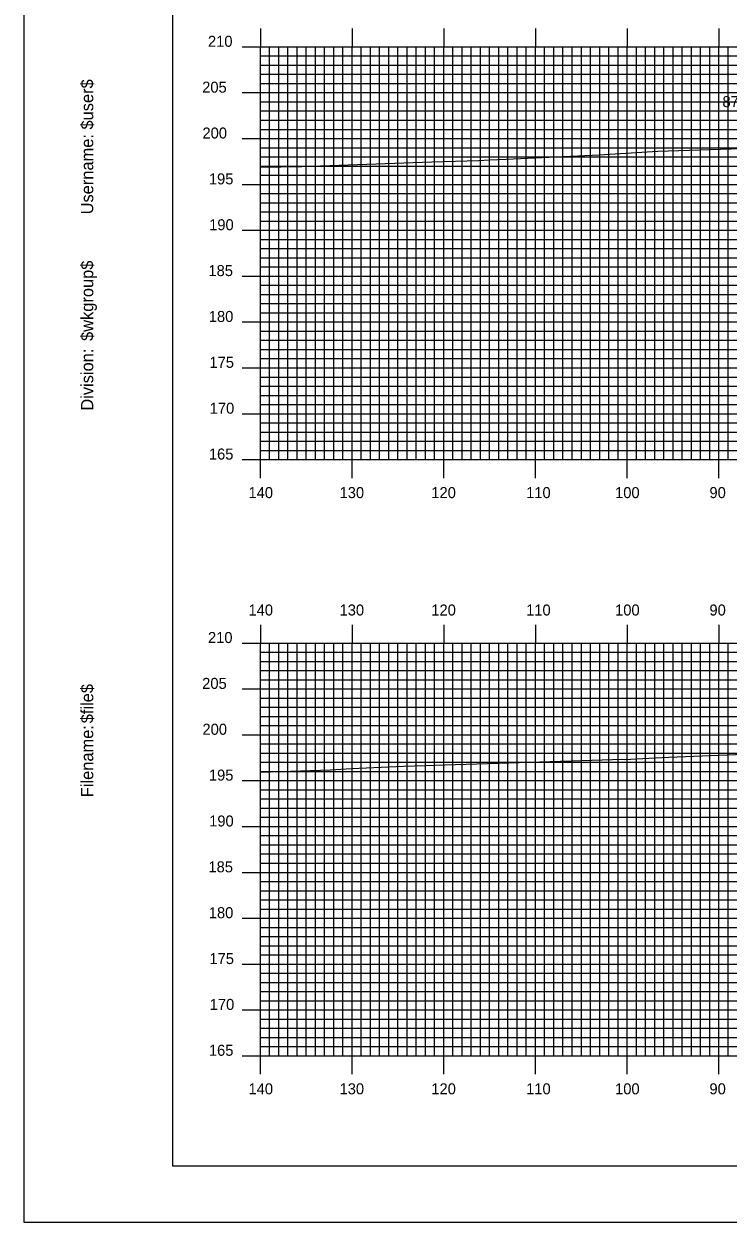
# Model space of a CAD drawing. Extents: x 1795633 to 1795976, y 442591 to 442811.
# Drawn here: x 1795633.1 to 1795709.9, y 442590.5 to 442721.2 of the extents above; entities that cross this region are included whole.
import ezdxf

# ---------------------------------------------------------------- set-up
doc = ezdxf.new("R2010")
doc.units = 0
for name, color, linetype in [('BORDER', 7, 'Continuous'), ('D_Text_Standard', 7, 'Continuous'), ('H_V ANNOTATION', 7, 'Continuous'), ('MAJOR', 7, 'Continuous'), ('MINOR', 7, 'Continuous'), ('PLOT BOUNDARY', 7, 'Continuous'), ('S_Roadway_Centerline', 7, 'Continuous')]:
    doc.layers.add(name, color=color, linetype=linetype)

msp = doc.modelspace()

# ---------------------------------------------------------------- linework, layer by layer
at = {"layer": 'BORDER'}
msp.add_lwpolyline([(1795649.28, 442596.67), (1795969.28, 442596.67), (1795969.28, 442806.67), (1795649.28, 442806.67)], close=True, dxfattribs=at)
at = {"layer": 'MAJOR'}
for p, q in [((1795658.88, 442720.67), (1795658.88, 442718.67)), ((1795668.88, 442720.67), (1795668.88, 442718.67)), ((1795678.88, 442720.67), (1795678.88, 442718.67)), ((1795688.88, 442720.67), (1795688.88, 442718.67)), ((1795698.88, 442720.67), (1795698.88, 442718.67)), ((1795708.88, 442720.67), (1795708.88, 442718.67)), ((1795656.88, 442718.67), (1795658.88, 442718.67)), ((1795658.88, 442718.67), (1795938.88, 442718.67)), ((1795658.88, 442673.67), (1795658.88, 442718.67)), ((1795658.88, 442673.67), (1795658.88, 442718.67)), ((1795658.88, 442718.67), (1795938.88, 442718.67)), ((1795668.88, 442673.67), (1795668.88, 442718.67)), ((1795678.88, 442673.67), (1795678.88, 442718.67)), ((1795688.88, 442673.67), (1795688.88, 442718.67)), ((1795698.88, 442673.67), (1795698.88, 442718.67)), ((1795708.88, 442673.67), (1795708.88, 442718.67)), ((1795656.88, 442713.67), (1795658.88, 442713.67)), ((1795658.88, 442713.67), (1795938.88, 442713.67)), ((1795656.88, 442708.67), (1795658.88, 442708.67)), ((1795658.88, 442708.67), (1795938.88, 442708.67)), ((1795656.88, 442703.67), (1795658.88, 442703.67)), ((1795658.88, 442703.67), (1795938.88, 442703.67)), ((1795656.88, 442698.67), (1795658.88, 442698.67)), ((1795658.88, 442698.67), (1795938.88, 442698.67)), ((1795656.88, 442693.67), (1795658.88, 442693.67)), ((1795658.88, 442693.67), (1795938.88, 442693.67)), ((1795656.88, 442688.67), (1795658.88, 442688.67)), ((1795658.88, 442688.67), (1795938.88, 442688.67)), ((1795656.88, 442683.67), (1795658.88, 442683.67)), ((1795658.88, 442683.67), (1795938.88, 442683.67)), ((1795656.88, 442678.67), (1795658.88, 442678.67)), ((1795658.88, 442678.67), (1795938.88, 442678.67)), ((1795656.88, 442673.67), (1795658.88, 442673.67)), ((1795658.88, 442673.67), (1795938.88, 442673.67)), ((1795658.88, 442673.67), (1795938.88, 442673.67)), ((1795658.88, 442671.66), (1795658.88, 442673.67)), ((1795668.88, 442671.66), (1795668.88, 442673.67)), ((1795678.88, 442671.66), (1795678.88, 442673.67)), ((1795688.88, 442671.66), (1795688.88, 442673.67)), ((1795698.88, 442671.66), (1795698.88, 442673.67)), ((1795708.88, 442671.66), (1795708.88, 442673.67)), ((1795658.88, 442655.67), (1795658.88, 442653.67)), ((1795668.88, 442655.67), (1795668.88, 442653.67)), ((1795678.88, 442655.67), (1795678.88, 442653.67)), ((1795688.88, 442655.67), (1795688.88, 442653.67)), ((1795698.88, 442655.67), (1795698.88, 442653.67)), ((1795708.88, 442655.67), (1795708.88, 442653.67)), ((1795656.88, 442653.67), (1795658.88, 442653.67)), ((1795658.88, 442653.67), (1795938.88, 442653.67)), ((1795658.88, 442608.67), (1795658.88, 442653.67)), ((1795658.88, 442608.67), (1795658.88, 442653.67)), ((1795658.88, 442653.67), (1795938.88, 442653.67)), ((1795668.88, 442608.67), (1795668.88, 442653.67)), ((1795678.88, 442608.67), (1795678.88, 442653.67)), ((1795688.88, 442608.67), (1795688.88, 442653.67)), ((1795698.88, 442608.67), (1795698.88, 442653.67)), ((1795708.88, 442608.67), (1795708.88, 442653.67)), ((1795656.88, 442648.67), (1795658.88, 442648.67)), ((1795658.88, 442648.67), (1795938.88, 442648.67)), ((1795656.88, 442643.67), (1795658.88, 442643.67)), ((1795658.88, 442643.67), (1795938.88, 442643.67)), ((1795656.88, 442638.67), (1795658.88, 442638.67)), ((1795658.88, 442638.67), (1795938.88, 442638.67)), ((1795656.88, 442633.67), (1795658.88, 442633.67)), ((1795658.88, 442633.67), (1795938.88, 442633.67)), ((1795656.88, 442628.67), (1795658.88, 442628.67)), ((1795658.88, 442628.67), (1795938.88, 442628.67)), ((1795656.88, 442623.67), (1795658.88, 442623.67)), ((1795658.88, 442623.67), (1795938.88, 442623.67)), ((1795656.88, 442618.67), (1795658.88, 442618.67)), ((1795658.88, 442618.67), (1795938.88, 442618.67)), ((1795656.88, 442613.67), (1795658.88, 442613.67)), ((1795658.88, 442613.67), (1795938.88, 442613.67)), ((1795656.88, 442608.67), (1795658.88, 442608.67)), ((1795658.88, 442608.67), (1795938.88, 442608.67)), ((1795658.88, 442608.67), (1795938.88, 442608.67)), ((1795658.88, 442606.66), (1795658.88, 442608.67)), ((1795668.88, 442606.66), (1795668.88, 442608.67)), ((1795678.88, 442606.66), (1795678.88, 442608.67)), ((1795688.88, 442606.66), (1795688.88, 442608.67)), ((1795698.88, 442606.66), (1795698.88, 442608.67)), ((1795708.88, 442606.66), (1795708.88, 442608.67))]:
    msp.add_line(p, q, dxfattribs=at)
at = {"layer": 'MINOR'}
for p, q in [((1795659.88, 442673.67), (1795659.88, 442718.67)), ((1795660.88, 442673.67), (1795660.88, 442718.67)), ((1795661.88, 442673.67), (1795661.88, 442718.67)), ((1795662.88, 442673.67), (1795662.88, 442718.67)), ((1795663.88, 442673.67), (1795663.88, 442718.67)), ((1795664.88, 442673.67), (1795664.88, 442718.67)), ((1795665.88, 442673.67), (1795665.88, 442718.67)), ((1795666.88, 442673.67), (1795666.88, 442718.67)), ((1795667.88, 442673.67), (1795667.88, 442718.67)), ((1795669.88, 442673.67), (1795669.88, 442718.67)), ((1795670.88, 442673.67), (1795670.88, 442718.67)), ((1795671.88, 442673.67), (1795671.88, 442718.67)), ((1795672.88, 442673.67), (1795672.88, 442718.67)), ((1795673.88, 442673.67), (1795673.88, 442718.67)), ((1795674.88, 442673.67), (1795674.88, 442718.67)), ((1795675.88, 442673.67), (1795675.88, 442718.67)), ((1795676.88, 442673.67), (1795676.88, 442718.67)), ((1795677.88, 442673.67), (1795677.88, 442718.67)), ((1795679.88, 442673.67), (1795679.88, 442718.67)), ((1795680.88, 442673.67), (1795680.88, 442718.67)), ((1795681.88, 442673.67), (1795681.88, 442718.67)), ((1795682.88, 442673.67), (1795682.88, 442718.67)), ((1795683.88, 442673.67), (1795683.88, 442718.67)), ((1795684.88, 442673.67), (1795684.88, 442718.67)), ((1795685.88, 442673.67), (1795685.88, 442718.67)), ((1795686.88, 442673.67), (1795686.88, 442718.67)), ((1795687.88, 442673.67), (1795687.88, 442718.67)), ((1795689.88, 442673.67), (1795689.88, 442718.67)), ((1795690.88, 442673.67), (1795690.88, 442718.67)), ((1795691.88, 442673.67), (1795691.88, 442718.67)), ((1795692.88, 442673.67), (1795692.88, 442718.67)), ((1795693.88, 442673.67), (1795693.88, 442718.67)), ((1795694.88, 442673.67), (1795694.88, 442718.67)), ((1795695.88, 442673.67), (1795695.88, 442718.67)), ((1795696.88, 442673.67), (1795696.88, 442718.67)), ((1795697.88, 442673.67), (1795697.88, 442718.67)), ((1795699.88, 442673.67), (1795699.88, 442718.67)), ((1795700.88, 442673.67), (1795700.88, 442718.67)), ((1795701.88, 442673.67), (1795701.88, 442718.67)), ((1795702.88, 442673.67), (1795702.88, 442718.67)), ((1795703.88, 442673.67), (1795703.88, 442718.67)), ((1795704.88, 442673.67), (1795704.88, 442718.67)), ((1795705.88, 442673.67), (1795705.88, 442718.67)), ((1795706.88, 442673.67), (1795706.88, 442718.67)), ((1795707.88, 442673.67), (1795707.88, 442718.67)), ((1795709.88, 442673.67), (1795709.88, 442718.67)), ((1795658.88, 442717.67), (1795938.88, 442717.67)), ((1795658.88, 442717.67), (1795660.88, 442717.67)), ((1795658.88, 442716.67), (1795938.88, 442716.67)), ((1795658.88, 442716.67), (1795660.88, 442716.67)), ((1795658.88, 442715.67), (1795938.88, 442715.67)), ((1795658.88, 442715.67), (1795660.88, 442715.67)), ((1795658.88, 442714.67), (1795938.88, 442714.67)), ((1795658.88, 442714.67), (1795660.88, 442714.67)), ((1795658.88, 442712.67), (1795938.88, 442712.67)), ((1795658.88, 442712.67), (1795660.88, 442712.67)), ((1795658.88, 442711.67), (1795938.88, 442711.67)), ((1795658.88, 442711.67), (1795660.88, 442711.67)), ((1795658.88, 442710.67), (1795938.88, 442710.67)), ((1795658.88, 442710.67), (1795660.88, 442710.67)), ((1795658.88, 442709.67), (1795938.88, 442709.67)), ((1795658.88, 442709.67), (1795660.88, 442709.67)), ((1795658.88, 442707.67), (1795938.88, 442707.67)), ((1795658.88, 442707.67), (1795660.88, 442707.67)), ((1795658.88, 442706.67), (1795938.88, 442706.67)), ((1795658.88, 442706.67), (1795660.88, 442706.67)), ((1795658.88, 442705.67), (1795938.88, 442705.67)), ((1795658.88, 442705.67), (1795660.88, 442705.67)), ((1795658.88, 442704.67), (1795938.88, 442704.67)), ((1795658.88, 442704.67), (1795660.88, 442704.67)), ((1795658.88, 442702.67), (1795938.88, 442702.67)), ((1795658.88, 442702.67), (1795660.88, 442702.67)), ((1795658.88, 442701.67), (1795938.88, 442701.67)), ((1795658.88, 442701.67), (1795660.88, 442701.67)), ((1795658.88, 442700.67), (1795938.88, 442700.67)), ((1795658.88, 442700.67), (1795660.88, 442700.67)), ((1795658.88, 442699.67), (1795938.88, 442699.67)), ((1795658.88, 442699.67), (1795660.88, 442699.67)), ((1795658.88, 442697.67), (1795938.88, 442697.67)), ((1795658.88, 442697.67), (1795660.88, 442697.67)), ((1795658.88, 442696.67), (1795938.88, 442696.67)), ((1795658.88, 442696.67), (1795660.88, 442696.67)), ((1795658.88, 442695.67), (1795938.88, 442695.67)), ((1795658.88, 442695.67), (1795660.88, 442695.67)), ((1795658.88, 442694.67), (1795938.88, 442694.67)), ((1795658.88, 442694.67), (1795660.88, 442694.67)), ((1795658.88, 442692.67), (1795938.88, 442692.67)), ((1795658.88, 442692.67), (1795660.88, 442692.67)), ((1795658.88, 442691.67), (1795938.88, 442691.67)), ((1795658.88, 442691.67), (1795660.88, 442691.67)), ((1795658.88, 442690.67), (1795938.88, 442690.67)), ((1795658.88, 442690.67), (1795660.88, 442690.67)), ((1795658.88, 442689.67), (1795938.88, 442689.67)), ((1795658.88, 442689.67), (1795660.88, 442689.67)), ((1795658.88, 442687.67), (1795938.88, 442687.67)), ((1795658.88, 442687.67), (1795660.88, 442687.67)), ((1795658.88, 442686.67), (1795938.88, 442686.67)), ((1795658.88, 442686.67), (1795660.88, 442686.67)), ((1795658.88, 442685.67), (1795938.88, 442685.67)), ((1795658.88, 442685.67), (1795660.88, 442685.67)), ((1795658.88, 442684.67), (1795938.88, 442684.67)), ((1795658.88, 442684.67), (1795660.88, 442684.67)), ((1795658.88, 442682.67), (1795938.88, 442682.67)), ((1795658.88, 442682.67), (1795660.88, 442682.67)), ((1795658.88, 442681.67), (1795938.88, 442681.67)), ((1795658.88, 442681.67), (1795660.88, 442681.67)), ((1795658.88, 442680.67), (1795938.88, 442680.67)), ((1795658.88, 442680.67), (1795660.88, 442680.67)), ((1795658.88, 442679.67), (1795938.88, 442679.67)), ((1795658.88, 442679.67), (1795660.88, 442679.67)), ((1795658.88, 442677.67), (1795938.88, 442677.67)), ((1795658.88, 442677.67), (1795660.88, 442677.67)), ((1795658.88, 442676.67), (1795938.88, 442676.67)), ((1795658.88, 442676.67), (1795660.88, 442676.67)), ((1795658.88, 442675.67), (1795938.88, 442675.67)), ((1795658.88, 442675.67), (1795660.88, 442675.67)), ((1795658.88, 442674.67), (1795938.88, 442674.67)), ((1795658.88, 442674.67), (1795660.88, 442674.67)), ((1795658.88, 442652.67), (1795938.88, 442652.67)), ((1795658.88, 442652.67), (1795660.88, 442652.67)), ((1795659.88, 442608.67), (1795659.88, 442653.67)), ((1795660.88, 442608.67), (1795660.88, 442653.67)), ((1795661.88, 442608.67), (1795661.88, 442653.67)), ((1795662.88, 442608.67), (1795662.88, 442653.67)), ((1795663.88, 442608.67), (1795663.88, 442653.67)), ((1795664.88, 442608.67), (1795664.88, 442653.67)), ((1795665.88, 442608.67), (1795665.88, 442653.67)), ((1795666.88, 442608.67), (1795666.88, 442653.67)), ((1795667.88, 442608.67), (1795667.88, 442653.67)), ((1795669.88, 442608.67), (1795669.88, 442653.67)), ((1795670.88, 442608.67), (1795670.88, 442653.67)), ((1795671.88, 442608.67), (1795671.88, 442653.67)), ((1795672.88, 442608.67), (1795672.88, 442653.67)), ((1795673.88, 442608.67), (1795673.88, 442653.67)), ((1795674.88, 442608.67), (1795674.88, 442653.67)), ((1795675.88, 442608.67), (1795675.88, 442653.67)), ((1795676.88, 442608.67), (1795676.88, 442653.67)), ((1795677.88, 442608.67), (1795677.88, 442653.67)), ((1795679.88, 442608.67), (1795679.88, 442653.67)), ((1795680.88, 442608.67), (1795680.88, 442653.67)), ((1795681.88, 442608.67), (1795681.88, 442653.67)), ((1795682.88, 442608.67), (1795682.88, 442653.67)), ((1795683.88, 442608.67), (1795683.88, 442653.67)), ((1795684.88, 442608.67), (1795684.88, 442653.67)), ((1795685.88, 442608.67), (1795685.88, 442653.67)), ((1795686.88, 442608.67), (1795686.88, 442653.67)), ((1795687.88, 442608.67), (1795687.88, 442653.67)), ((1795689.88, 442608.67), (1795689.88, 442653.67)), ((1795690.88, 442608.67), (1795690.88, 442653.67)), ((1795691.88, 442608.67), (1795691.88, 442653.67)), ((1795692.88, 442608.67), (1795692.88, 442653.67)), ((1795693.88, 442608.67), (1795693.88, 442653.67)), ((1795694.88, 442608.67), (1795694.88, 442653.67)), ((1795695.88, 442608.67), (1795695.88, 442653.67)), ((1795696.88, 442608.67), (1795696.88, 442653.67)), ((1795697.88, 442608.67), (1795697.88, 442653.67)), ((1795699.88, 442608.67), (1795699.88, 442653.67)), ((1795700.88, 442608.67), (1795700.88, 442653.67)), ((1795701.88, 442608.67), (1795701.88, 442653.67)), ((1795702.88, 442608.67), (1795702.88, 442653.67)), ((1795703.88, 442608.67), (1795703.88, 442653.67)), ((1795704.88, 442608.67), (1795704.88, 442653.67)), ((1795705.88, 442608.67), (1795705.88, 442653.67)), ((1795706.88, 442608.67), (1795706.88, 442653.67)), ((1795707.88, 442608.67), (1795707.88, 442653.67)), ((1795709.88, 442608.67), (1795709.88, 442653.67)), ((1795658.88, 442651.67), (1795938.88, 442651.67)), ((1795658.88, 442651.67), (1795660.88, 442651.67)), ((1795658.88, 442650.67), (1795938.88, 442650.67)), ((1795658.88, 442650.67), (1795660.88, 442650.67)), ((1795658.88, 442649.67), (1795938.88, 442649.67)), ((1795658.88, 442649.67), (1795660.88, 442649.67)), ((1795658.88, 442647.67), (1795938.88, 442647.67)), ((1795658.88, 442647.67), (1795660.88, 442647.67)), ((1795658.88, 442646.67), (1795938.88, 442646.67)), ((1795658.88, 442646.67), (1795660.88, 442646.67)), ((1795658.88, 442645.67), (1795938.88, 442645.67)), ((1795658.88, 442645.67), (1795660.88, 442645.67)), ((1795658.88, 442644.67), (1795938.88, 442644.67)), ((1795658.88, 442644.67), (1795660.88, 442644.67)), ((1795658.88, 442642.67), (1795938.88, 442642.67)), ((1795658.88, 442642.67), (1795660.88, 442642.67)), ((1795658.88, 442641.67), (1795938.88, 442641.67)), ((1795658.88, 442641.67), (1795660.88, 442641.67)), ((1795658.88, 442640.67), (1795938.88, 442640.67)), ((1795658.88, 442640.67), (1795660.88, 442640.67)), ((1795658.88, 442639.67), (1795938.88, 442639.67)), ((1795658.88, 442639.67), (1795660.88, 442639.67)), ((1795658.88, 442637.67), (1795938.88, 442637.67)), ((1795658.88, 442637.67), (1795660.88, 442637.67)), ((1795658.88, 442636.67), (1795938.88, 442636.67)), ((1795658.88, 442636.67), (1795660.88, 442636.67)), ((1795658.88, 442635.67), (1795938.88, 442635.67)), ((1795658.88, 442635.67), (1795660.88, 442635.67)), ((1795658.88, 442634.67), (1795938.88, 442634.67)), ((1795658.88, 442634.67), (1795660.88, 442634.67)), ((1795658.88, 442632.67), (1795938.88, 442632.67)), ((1795658.88, 442632.67), (1795660.88, 442632.67)), ((1795658.88, 442631.67), (1795938.88, 442631.67)), ((1795658.88, 442631.67), (1795660.88, 442631.67)), ((1795658.88, 442630.67), (1795938.88, 442630.67)), ((1795658.88, 442630.67), (1795660.88, 442630.67)), ((1795658.88, 442629.67), (1795938.88, 442629.67)), ((1795658.88, 442629.67), (1795660.88, 442629.67)), ((1795658.88, 442627.67), (1795938.88, 442627.67)), ((1795658.88, 442627.67), (1795660.88, 442627.67)), ((1795658.88, 442626.67), (1795938.88, 442626.67)), ((1795658.88, 442626.67), (1795660.88, 442626.67)), ((1795658.88, 442625.67), (1795938.88, 442625.67)), ((1795658.88, 442625.67), (1795660.88, 442625.67)), ((1795658.88, 442624.67), (1795938.88, 442624.67)), ((1795658.88, 442624.67), (1795660.88, 442624.67)), ((1795658.88, 442622.67), (1795938.88, 442622.67)), ((1795658.88, 442622.67), (1795660.88, 442622.67)), ((1795658.88, 442621.67), (1795938.88, 442621.67)), ((1795658.88, 442621.67), (1795660.88, 442621.67)), ((1795658.88, 442620.67), (1795938.88, 442620.67)), ((1795658.88, 442620.67), (1795660.88, 442620.67)), ((1795658.88, 442619.67), (1795938.88, 442619.67)), ((1795658.88, 442619.67), (1795660.88, 442619.67)), ((1795658.88, 442617.67), (1795938.88, 442617.67)), ((1795658.88, 442617.67), (1795660.88, 442617.67)), ((1795658.88, 442616.67), (1795938.88, 442616.67)), ((1795658.88, 442616.67), (1795660.88, 442616.67)), ((1795658.88, 442615.67), (1795938.88, 442615.67)), ((1795658.88, 442615.67), (1795660.88, 442615.67)), ((1795658.88, 442614.67), (1795938.88, 442614.67)), ((1795658.88, 442614.67), (1795660.88, 442614.67)), ((1795658.88, 442612.67), (1795938.88, 442612.67)), ((1795658.88, 442612.67), (1795660.88, 442612.67)), ((1795658.88, 442611.67), (1795938.88, 442611.67)), ((1795658.88, 442611.67), (1795660.88, 442611.67)), ((1795658.88, 442610.67), (1795938.88, 442610.67)), ((1795658.88, 442610.67), (1795660.88, 442610.67)), ((1795658.88, 442609.67), (1795938.88, 442609.67)), ((1795658.88, 442609.67), (1795660.88, 442609.67))]:
    msp.add_line(p, q, dxfattribs=at)
at = {"layer": 'PLOT BOUNDARY'}
msp.add_lwpolyline([(1795633.09, 442590.55), (1795973.09, 442590.55), (1795973.09, 442810.55), (1795633.09, 442810.55)], close=True, dxfattribs=at)
at = {"layer": 'S_Roadway_Centerline'}
for points in [[(1795658.88, 442705.54), (1795663.39, 442705.62), (1795677.56, 442706.12), (1795682.71, 442706.27), (1795683.83, 442706.33), (1795685.69, 442706.42), (1795695.82, 442706.89), (1795702.23, 442707.28), (1795717.06, 442707.78)], [(1795658.88, 442639.58), (1795666.54, 442639.85), (1795668.82, 442639.99), (1795674.49, 442640.25), (1795676.84, 442640.33), (1795678.99, 442640.39), (1795685.99, 442640.61), (1795698.42, 442641.02), (1795698.62, 442640.98), (1795701.24, 442641.11), (1795703.44, 442641.21), (1795721.55, 442641.97)]]:
    msp.add_lwpolyline(points, dxfattribs=at)

# ---------------------------------------------------------------- texts
at = {"layer": 'BORDER'}
for s, p in [('$user$', (1795640.65, 442709.65)), ('Username:', (1795640.65, 442700.4)), ('$wkgroup$', (1795640.65, 442686.6)), ('Division:', (1795640.65, 442679)), ('$file$', (1795640.65, 442644.92)), ('Filename:', (1795640.65, 442636.86))]:
    msp.add_text(s, height=1.339, rotation=90, dxfattribs=at).set_placement(p)
at = {"layer": 'D_Text_Standard'}
msp.add_text("87.8'", height=1.2, dxfattribs=at).set_placement((1795709.27, 442712.09))
at = {"layer": 'H_V ANNOTATION'}
for s, p in [('210', (1795653.16, 442718.67)), ('205', (1795652.53, 442713.67)), ('200', (1795652.56, 442708.67)), ('195', (1795653.26, 442703.67)), ('190', (1795653.29, 442698.67)), ('185', (1795653.21, 442693.67)), ('180', (1795653.25, 442688.67)), ('175', (1795653.32, 442683.67)), ('170', (1795653.35, 442678.67)), ('165', (1795653.26, 442673.67)), ('140', (1795657.58, 442669.47)), ('130', (1795667.51, 442669.47)), ('120', (1795677.52, 442669.47)), ('110', (1795687.86, 442669.47)), ('100', (1795697.56, 442669.47)), ('90', (1795707.85, 442669.47)), ('140', (1795657.58, 442656.67)), ('130', (1795667.51, 442656.67)), ('120', (1795677.52, 442656.67)), ('110', (1795687.86, 442656.67)), ('100', (1795697.56, 442656.67)), ('90', (1795707.85, 442656.67)), ('210', (1795653.16, 442653.67)), ('205', (1795652.53, 442648.67)), ('200', (1795652.56, 442643.67)), ('195', (1795653.26, 442638.67)), ('190', (1795653.29, 442633.67)), ('185', (1795653.21, 442628.67)), ('180', (1795653.25, 442623.67)), ('175', (1795653.32, 442618.67)), ('170', (1795653.35, 442613.67)), ('165', (1795653.26, 442608.67)), ('140', (1795657.58, 442604.47)), ('130', (1795667.51, 442604.47)), ('120', (1795677.52, 442604.47)), ('110', (1795687.86, 442604.47)), ('100', (1795697.56, 442604.47)), ('90', (1795707.85, 442604.47))]:
    msp.add_text(s, height=1.2, dxfattribs=at).set_placement(p)
at = {"layer": 'MAJOR'}
for p in [(1795658.87, 442673.67), (1795658.87, 442608.67)]:
    msp.add_text('-', height=0.012, dxfattribs=at).set_placement(p)

doc.saveas('drawing.dxf')
